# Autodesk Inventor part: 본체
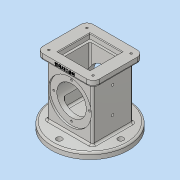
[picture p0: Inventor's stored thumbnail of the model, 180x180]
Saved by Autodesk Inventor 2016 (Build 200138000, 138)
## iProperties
Created: 2018-10
Part Number: 본체
Material: 알루미늄 6061
Document SubType Name: Modeling
Designer: Administrator
Density: 2.7 g/cm^3
Appearance: 알루미늄 - 평지
Mass: 984.575 g
Surface Area: 743.905 cm^2
Volume: 364.657 cm^3
Author: Administrator
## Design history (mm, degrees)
sketch "스케치1"
  geometry: C1 r 62.5 at (0, 0); 1 further point
  constraints: 1 centre point, 1 coincident
  dimensions: "d0" = 125 diameter of C1
extrude "돌출1" new body sketch "스케치1" distance "d1" = 10; taper "d2" = 0 deg
sketch "스케치2"
  geometry: L1 (-37, 33)-(37, 33); L2 (37, 33)-(37, -33); L3 (37, -33)-(-37, -33); L4 (-37, -33)-(-37, 33); L5 (-37, 33)-(37, -33); L6 (37, 33)-(-37, -33); 1 further point
  constraints: 12 end point, 2 midpoint, 2 parallel, 1 horizontal, 1 perpendicular
  dimensions: "d3" = 74 distance of L2.end L3.end; "d4" = 66 distance of L1.end L2.end
extrude "돌출2" join sketch "스케치2" distance "d5" = 88; taper "d6" = 0 deg
sketch "스케치3"
  geometry: L1 (-46, 41)-(46, 41); L2 (46, 41)-(46, -41); L3 (46, -41)-(-46, -41); L4 (-46, -41)-(-46, 41); L5 (-46, 41)-(46, -41); L6 (46, 41)-(-46, -41); 1 further point
  constraints: 12 end point, 2 midpoint, 2 parallel, 1 horizontal, 1 perpendicular
  dimensions: "d7" = 92 distance of L2.end L3.end; "d8" = 82 distance of L1.end L2.end
extrude "돌출3" join sketch "스케치3" distance "d9" = 10; taper "d10" = 0 deg
sketch "스케치4"
  geometry: L1 (-77, 54)-(79, 54); L2 (-62.5, 0)-(62.5, 0) reference; L3 (-33, 10)-(-33, 98) reference; L4 (-33, 89)-(-30, 89); L5 (-30, 89)-(-30, 78); L6 (-30, 78)-(30, 78); L7 (30, 78)-(30, 89); L8 (30, 89)-(33, 89); L9 (33, 10)-(33, 98) reference; L10 (-33, 89)-(-33, 54); L11 (33, 89)-(33, 54); L12 (-33, 54)-(33, 54); 1 further point
  constraints: 18 end point, 4 point on line, 3 perpendicular, 2 horizontal, 2 midpoint, 1 collinear
  dimensions: "d11" = 54 distance between parallel lines of L2 L1; "d12" = 70 diameter of L4 L1; "d13" = 48 diameter of L6 L1; "d14" = 3 distance of L4.start L4.end; "d15" = 3 distance of L7.end L8.end; "d16" = 70 diameter of L8 L1 (derived)
revolve "회전1" sketch "스케치4" stored, may be unused: angle "d17" = 90 deg
sketch "스케치5"
  geometry: L1 (-26, 26)-(26, 26); L2 (26, 26)-(26, -26); L3 (26, -26)-(-26, -26); L4 (-26, -26)-(-26, 26); L5 (-26, 26)-(26, -26); L6 (26, 26)-(-26, -26); 1 further point
  constraints: 12 end point, 2 midpoint, 2 parallel, 1 horizontal, 1 perpendicular
  dimensions: "d18" = 52 distance of L2.end L3.end; "d19" = 52 distance of L1.end L2.end
extrude "돌출4" cut sketch "스케치5" distance "d20" = 8; taper "d21" = 0 deg
sketch "스케치6"
  geometry: L1 (-22, 22)-(22, 22); L2 (22, 22)-(22, -22); L3 (22, -22)-(-22, -22); L4 (-22, -22)-(-22, 22); L5 (-22, 22)-(22, -22); L6 (22, 22)-(-22, -22); 1 further point
  constraints: 12 end point, 2 midpoint, 2 parallel, 1 horizontal, 1 perpendicular
  dimensions: "d22" = 44 distance of L2.end L3.end; "d23" = 44 distance of L1.end L2.end
extrude "돌출5" cut sketch "스케치6" distance "d24" = 74; taper "d25" = 0 deg
sketch "스케치7"
  geometry: A1 r 29 centre (0, 0) between (0, 29) and (29, 0); 3 further points
  constraints: 4 point on circle, 1 centre point
  dimensions: "d26" = 58 diameter of A1
hole "구멍1" sketch "스케치7" at (0, 29), (29, 0), (-29, 0), (0, -29) diameter "d27" = 3.242; stored, may be unused: countersink angle "d31" = 90 deg, drill point angle "d33" = 118 deg; dims "d28" = 4, "d29" = 4, "d30" = 2, "d32" = 6
sketch "스케치8"
  geometry: L1 (10, -29.5)-(10, 95.5) reference; 3 further points
  dimensions: "d34" = 37 distance from line of L1 point (-27, 33); "d35" = 43 distance of point (-27, 33) point (-70, 33)
hole "구멍2" sketch "스케치8" at (-27, 33), (-70, 33) diameter "d36" = 4.134; stored, may be unused: countersink angle "d40" = 90 deg, drill point angle "d42" = 118 deg; dims "d37" = 15, "d38" = 4, "d39" = 2, "d41" = 15
sketch "스케치9"
  geometry: C1 r 28 at (0, 0); 1 further point
  constraints: 1 centre point, 1 coincident
  dimensions: "d43" = 56 diameter of C1
extrude "돌출6" cut sketch "스케치9" distance "d44" = 18; taper "d45" = -10 deg
sketch "스케치10"
  geometry: A1 r 50 centre (0, 0) between (-50, 0) and (0, 50); 3 further points
  constraints: 4 point on circle, 1 centre point, 1 coincident
  dimensions: "d46" = 100 diameter of A1
hole "구멍3" sketch "스케치10" at (-50, 0), (0, 50), (50, 0), (0, -50) diameter "d47" = 9; stored, may be unused: countersink angle "d51" = 90 deg, drill point angle "d53" = 118 deg; dims "d48" = 10, "d49" = 4, "d50" = 2, "d52" = 10
fillet "모깎기1" dims "d54" = 10
sketch "스케치11"
  geometry: A1 r 10 centre (-36, 31) between (-36, 41) and (-46, 31) reference; A2 r 10 centre (36, 31) between (46, 31) and (36, 41) reference; A3 r 10 centre (36, -31) between (36, -41) and (46, -31) reference; A4 r 10 centre (-36, -31) between (-46, -31) and (-36, -41) reference; 5 further points
  constraints: 4 coincident
hole "구멍4" sketch "스케치11" at (-36, 31), (36, 31), (36, -31), (-36, -31) diameter "d55" = 3.242; stored, may be unused: countersink angle "d59" = 90 deg, drill point angle "d61" = 118 deg; dims "d56" = 4, "d57" = 4, "d58" = 2, "d60" = 6
chamfer "모따기1" distance "d62" = 1; stored, may be unused: second distance "d63" = 2, angle "d64" = 45 deg
fillet "모깎기2" dims "d65" = 3, "d66" = 3
fillet "모깎기3" dims "d67" = 3
sketch "스케치12"
  geometry: L1 (-10, 0)-(-10, -7) reference; L2 (0, 0)-(72, 0) reference; 2 further points
  constraints: 1 other
  dimensions: "d68" = 46 distance from line of point (36, -4) L1; "d69" = 4 distance from line of point (36, -4) L2
feature "엠보싱1" sketch "스케치12" dims "d70" = 0.5, "d71" = 0
node "솔리드1"
mirror "대칭1"
